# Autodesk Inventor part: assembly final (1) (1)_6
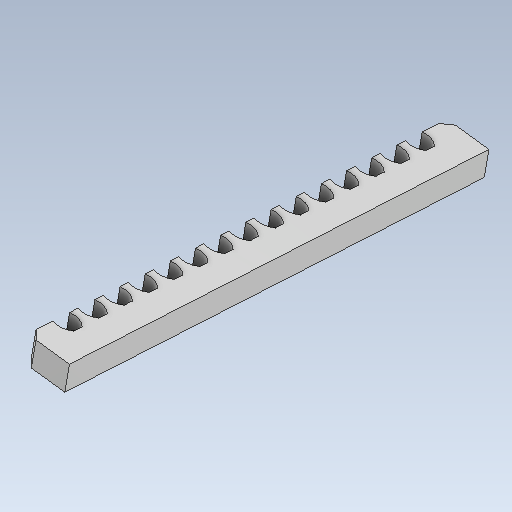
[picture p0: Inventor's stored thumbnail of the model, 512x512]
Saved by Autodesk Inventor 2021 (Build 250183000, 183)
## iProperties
Created: 2021-07
Part Number: assembly final (1) (1)_6
Material: Generic
Document SubType Name: Modeling
Designer: TARUN
Density: 1 g/cm^3
Appearance: Default
Author: TARUN
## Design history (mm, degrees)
feature "Base1"
body "Solid1"
